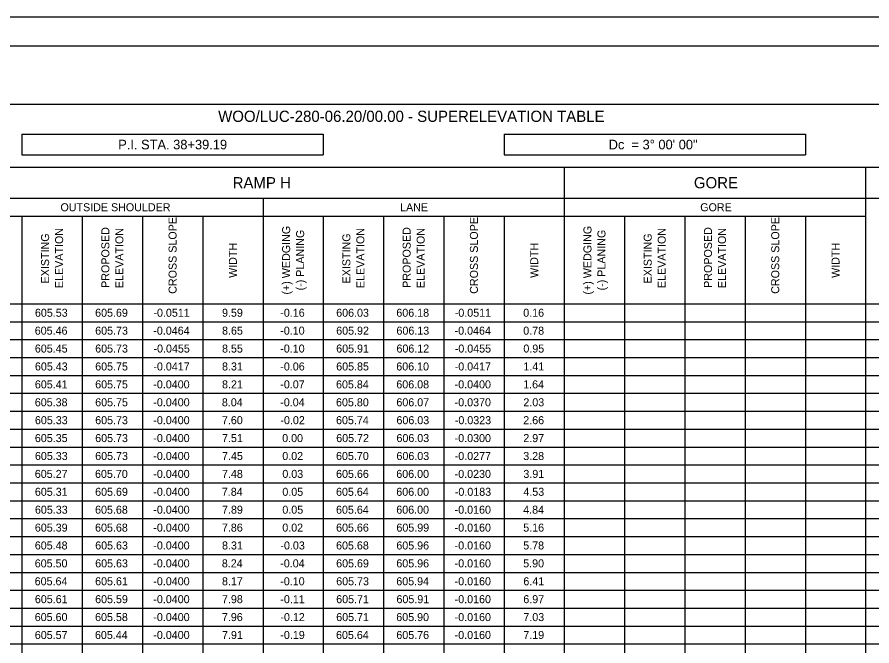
# Model space of a CAD drawing. Extents: x 0 to 34, y 0 to 22.
# Drawn here: x 7.6 to 22.56, y 11.01 to 22 of the extents above; entities that cross this region are included whole.
import ezdxf

# ---------------------------------------------------------------- set-up
doc = ezdxf.new("R2010")
doc.units = 0
for name, color, linetype in [('Default', 7, 'Continuous'), ('SH_Border', 7, 'Continuous'), ('SH_Cut_Line', 7, 'Continuous')]:
    doc.layers.add(name, color=color, linetype=linetype)

msp = doc.modelspace()

# ---------------------------------------------------------------- linework, layer by layer
at = {"layer": 'Default'}
for p, q in [((6.635, 20.48), (26.861, 20.48)), ((7.689, 19.953), (12.96, 19.953)), ((7.689, 19.953), (7.689, 19.591)), ((12.96, 19.953), (12.96, 19.591)), ((16.122, 19.953), (21.393, 19.953)), ((16.122, 19.953), (16.122, 19.591)), ((21.393, 19.953), (21.393, 19.591)), ((7.689, 19.591), (12.96, 19.591)), ((16.122, 19.591), (21.393, 19.591)), ((6.635, 19.376), (26.861, 19.376)), ((17.176, 19.376), (17.176, 1.522)), ((22.447, 19.376), (22.447, 1.522)), ((6.635, 18.833), (26.861, 18.833)), ((11.906, 18.833), (11.906, 1.522)), ((6.635, 18.52), (22.447, 18.52)), ((7.689, 18.52), (7.689, 1.522)), ((8.743, 18.52), (8.743, 1.522)), ((9.797, 18.52), (9.797, 1.522)), ((10.851, 18.52), (10.851, 1.522)), ((12.96, 18.52), (12.96, 1.522)), ((14.014, 18.52), (14.014, 1.522)), ((15.068, 18.52), (15.068, 1.522)), ((16.122, 18.52), (16.122, 1.522)), ((18.23, 18.52), (18.23, 1.522)), ((19.284, 18.52), (19.284, 1.522)), ((20.339, 18.52), (20.339, 1.522)), ((21.393, 18.52), (21.393, 1.522)), ((6.635, 16.988), (26.861, 16.988)), ((6.635, 16.675), (26.861, 16.675)), ((6.635, 16.362), (26.861, 16.362)), ((6.635, 16.049), (26.861, 16.049)), ((6.635, 15.736), (26.861, 15.736)), ((6.635, 15.424), (26.861, 15.424)), ((6.635, 15.111), (26.861, 15.111)), ((6.635, 14.798), (26.861, 14.798)), ((6.635, 14.485), (26.861, 14.485)), ((6.635, 14.172), (26.861, 14.172)), ((6.635, 13.859), (26.861, 13.859)), ((6.635, 13.546), (26.861, 13.546)), ((6.635, 13.233), (26.861, 13.233)), ((6.635, 12.92), (26.861, 12.92)), ((6.635, 12.607), (26.861, 12.607)), ((6.635, 12.294), (26.861, 12.294)), ((6.635, 11.981), (26.861, 11.981)), ((6.635, 11.668), (26.861, 11.668)), ((6.635, 11.355), (26.861, 11.355)), ((6.635, 11.042), (26.861, 11.042))]:
    msp.add_line(p, q, dxfattribs=at)
at = {"layer": 'SH_Border'}
msp.add_lwpolyline([(1.5, 21.5), (33.5, 21.5), (33.5, 0.5), (1.5, 0.5)], close=True, dxfattribs=at)
at = {"layer": 'SH_Cut_Line'}
msp.add_lwpolyline([(0, 0), (34, 0), (34, 22), (0, 22)], close=True, dxfattribs=at)

# ---------------------------------------------------------------- texts
at = {"layer": 'Default'}
for s, height, p in [('WOO/LUC-280-06.20/00.00 - SUPERELEVATION TABLE', 0.196, (11.121, 20.168)), ('P.I. STA. 38+39.19', 0.168, (9.373, 19.688)), ('Dc  = 3° 00\' 00"', 0.168, (17.952, 19.688)), ('RAMP H', 0.196, (11.374, 19.007)), ('GORE', 0.196, (19.443, 19.007)), ('OUTSIDE SHOULDER', 0.14, (8.363, 18.606)), ('LANE', 0.14, (14.304, 18.606)), ('GORE', 0.14, (19.554, 18.606)), ('605.53', 0.14, (7.916, 16.762)), ('605.69', 0.14, (8.969, 16.762)), ('-0.0511', 0.14, (9.989, 16.762)), ('9.59', 0.14, (11.189, 16.762)), ('-0.16', 0.14, (12.208, 16.762)), ('606.03', 0.14, (13.186, 16.762)), ('606.18', 0.14, (14.238, 16.762)), ('-0.0511', 0.14, (15.26, 16.762)), ('0.16', 0.14, (16.458, 16.762)), ('605.46', 0.14, (7.913, 16.449)), ('605.73', 0.14, (8.97, 16.449)), ('-0.0464', 0.14, (9.987, 16.449)), ('8.65', 0.14, (11.189, 16.449)), ('-0.10', 0.14, (12.207, 16.449)), ('605.92', 0.14, (13.186, 16.449)), ('606.13', 0.14, (14.24, 16.449)), ('-0.0464', 0.14, (15.257, 16.449)), ('0.78', 0.14, (16.458, 16.449)), ('605.45', 0.14, (7.915, 16.136)), ('605.73', 0.14, (8.97, 16.136)), ('-0.0455', 0.14, (9.99, 16.136)), ('8.55', 0.14, (11.189, 16.136)), ('-0.10', 0.14, (12.207, 16.136)), ('605.91', 0.14, (13.186, 16.136)), ('606.12', 0.14, (14.24, 16.136)), ('-0.0455', 0.14, (15.26, 16.136)), ('0.95', 0.14, (16.46, 16.136)), ('605.43', 0.14, (7.916, 15.823)), ('605.75', 0.14, (8.97, 15.823)), ('-0.0417', 0.14, (9.988, 15.823)), ('8.31', 0.14, (11.189, 15.823)), ('-0.06', 0.14, (12.208, 15.823)), ('605.85', 0.14, (13.186, 15.823)), ('606.10', 0.14, (14.237, 15.823)), ('-0.0417', 0.14, (15.259, 15.823)), ('1.41', 0.14, (16.46, 15.823)), ('605.41', 0.14, (7.915, 15.51)), ('605.75', 0.14, (8.97, 15.51)), ('-0.0400', 0.14, (9.987, 15.51)), ('8.21', 0.14, (11.189, 15.51)), ('-0.07', 0.14, (12.208, 15.51)), ('605.84', 0.14, (13.183, 15.51)), ('606.08', 0.14, (14.238, 15.51)), ('-0.0400', 0.14, (15.258, 15.51)), ('1.64', 0.14, (16.457, 15.51)), ('605.38', 0.14, (7.914, 15.197)), ('605.75', 0.14, (8.97, 15.197)), ('-0.0400', 0.14, (9.987, 15.197)), ('8.04', 0.14, (11.186, 15.197)), ('-0.04', 0.14, (12.207, 15.197)), ('605.80', 0.14, (13.183, 15.197)), ('606.07', 0.14, (14.239, 15.197)), ('-0.0370', 0.14, (15.258, 15.197)), ('2.03', 0.14, (16.46, 15.197)), ('605.33', 0.14, (7.916, 14.884)), ('605.73', 0.14, (8.97, 14.884)), ('-0.0400', 0.14, (9.987, 14.884)), ('7.60', 0.14, (11.187, 14.884)), ('-0.02', 0.14, (12.21, 14.884)), ('605.74', 0.14, (13.183, 14.884)), ('606.03', 0.14, (14.24, 14.884)), ('-0.0323', 0.14, (15.261, 14.884)), ('2.66', 0.14, (16.458, 14.884)), ('605.35', 0.14, (7.915, 14.571)), ('605.73', 0.14, (8.97, 14.571)), ('-0.0400', 0.14, (9.987, 14.571)), ('7.51', 0.14, (11.189, 14.571)), ('0.00', 0.14, (12.241, 14.571)), ('605.72', 0.14, (13.186, 14.571)), ('606.03', 0.14, (14.24, 14.571)), ('-0.0300', 0.14, (15.258, 14.571)), ('2.97', 0.14, (16.459, 14.571)), ('605.33', 0.14, (7.916, 14.258)), ('605.73', 0.14, (8.97, 14.258)), ('-0.0400', 0.14, (9.987, 14.258)), ('7.45', 0.14, (11.189, 14.258)), ('0.02', 0.14, (12.243, 14.258)), ('605.70', 0.14, (13.183, 14.258)), ('606.03', 0.14, (14.24, 14.258)), ('-0.0277', 0.14, (15.259, 14.258)), ('3.28', 0.14, (16.458, 14.258)), ('605.27', 0.14, (7.914, 13.945)), ('605.70', 0.14, (8.967, 13.945)), ('-0.0400', 0.14, (9.987, 13.945)), ('7.48', 0.14, (11.188, 13.945)), ('0.03', 0.14, (12.244, 13.945)), ('605.66', 0.14, (13.184, 13.945)), ('606.00', 0.14, (14.237, 13.945)), ('-0.0230', 0.14, (15.258, 13.945)), ('3.91', 0.14, (16.46, 13.945)), ('605.31', 0.14, (7.915, 13.632)), ('605.69', 0.14, (8.969, 13.632)), ('-0.0400', 0.14, (9.987, 13.632)), ('7.84', 0.14, (11.186, 13.632)), ('0.05', 0.14, (12.244, 13.632)), ('605.64', 0.14, (13.183, 13.632)), ('606.00', 0.14, (14.237, 13.632)), ('-0.0183', 0.14, (15.261, 13.632)), ('4.53', 0.14, (16.46, 13.632)), ('605.33', 0.14, (7.916, 13.319)), ('605.68', 0.14, (8.968, 13.319)), ('-0.0400', 0.14, (9.987, 13.319)), ('7.89', 0.14, (11.189, 13.319)), ('0.05', 0.14, (12.244, 13.319)), ('605.64', 0.14, (13.183, 13.319)), ('606.00', 0.14, (14.237, 13.319)), ('-0.0160', 0.14, (15.258, 13.319)), ('4.84', 0.14, (16.457, 13.319)), ('605.39', 0.14, (7.915, 13.006)), ('605.68', 0.14, (8.968, 13.006)), ('-0.0400', 0.14, (9.987, 13.006)), ('7.86', 0.14, (11.187, 13.006)), ('0.02', 0.14, (12.243, 13.006)), ('605.66', 0.14, (13.184, 13.006)), ('605.99', 0.14, (14.239, 13.006)), ('-0.0160', 0.14, (15.258, 13.006)), ('5.16', 0.14, (16.458, 13.006)), ('605.48', 0.14, (7.914, 12.694)), ('605.63', 0.14, (8.97, 12.694)), ('-0.0400', 0.14, (9.987, 12.694)), ('8.31', 0.14, (11.189, 12.694)), ('-0.03', 0.14, (12.21, 12.694)), ('605.68', 0.14, (13.184, 12.694)), ('605.96', 0.14, (14.238, 12.694)), ('-0.0160', 0.14, (15.258, 12.694)), ('5.78', 0.14, (16.458, 12.694)), ('605.50', 0.14, (7.913, 12.381)), ('605.63', 0.14, (8.97, 12.381)), ('-0.0400', 0.14, (9.987, 12.381)), ('8.24', 0.14, (11.186, 12.381)), ('-0.04', 0.14, (12.207, 12.381)), ('605.69', 0.14, (13.185, 12.381)), ('605.96', 0.14, (14.238, 12.381)), ('-0.0160', 0.14, (15.258, 12.381)), ('5.90', 0.14, (16.457, 12.381)), ('605.64', 0.14, (7.912, 12.068)), ('605.61', 0.14, (8.969, 12.068)), ('-0.0400', 0.14, (9.987, 12.068)), ('8.17', 0.14, (11.188, 12.068)), ('-0.10', 0.14, (12.207, 12.068)), ('605.73', 0.14, (13.186, 12.068)), ('605.94', 0.14, (14.237, 12.068)), ('-0.0160', 0.14, (15.258, 12.068)), ('6.41', 0.14, (16.46, 12.068)), ('605.61', 0.14, (7.915, 11.755)), ('605.59', 0.14, (8.969, 11.755)), ('-0.0400', 0.14, (9.987, 11.755)), ('7.98', 0.14, (11.188, 11.755)), ('-0.11', 0.14, (12.209, 11.755)), ('605.71', 0.14, (13.186, 11.755)), ('605.91', 0.14, (14.24, 11.755)), ('-0.0160', 0.14, (15.258, 11.755)), ('6.97', 0.14, (16.459, 11.755)), ('605.60', 0.14, (7.913, 11.442)), ('605.58', 0.14, (8.968, 11.442)), ('-0.0400', 0.14, (9.987, 11.442)), ('7.96', 0.14, (11.187, 11.442)), ('-0.12', 0.14, (12.21, 11.442)), ('605.71', 0.14, (13.186, 11.442)), ('605.90', 0.14, (14.237, 11.442)), ('-0.0160', 0.14, (15.258, 11.442)), ('7.03', 0.14, (16.46, 11.442)), ('605.57', 0.14, (7.914, 11.129)), ('605.44', 0.14, (8.966, 11.129)), ('-0.0400', 0.14, (9.987, 11.129)), ('7.91', 0.14, (11.189, 11.129)), ('-0.19', 0.14, (12.209, 11.129)), ('605.64', 0.14, (13.183, 11.129)), ('605.76', 0.14, (14.238, 11.129)), ('-0.0160', 0.14, (15.258, 11.129)), ('7.19', 0.14, (16.459, 11.129))]:
    msp.add_text(s, height=height, dxfattribs=at).set_placement(p)
for s, p in [('CROSS SLOPE', (10.394, 17.163)), ('CROSS SLOPE', (15.665, 17.163)), ('CROSS SLOPE', (20.936, 17.163)), ('ELEVATION', (8.409, 17.263)), ('PROPOSED ', (9.218, 17.267)), ('ELEVATION', (9.463, 17.263)), ('(+) WEDGING', (12.38, 17.15)), ('(-) PLANING', (12.625, 17.222)), ('ELEVATION', (13.679, 17.263)), ('PROPOSED ', (14.488, 17.267)), ('ELEVATION', (14.733, 17.263)), ('(+) WEDGING', (17.651, 17.15)), ('(-) PLANING', (17.896, 17.222)), ('ELEVATION', (18.95, 17.263)), ('PROPOSED ', (19.759, 17.267)), ('ELEVATION', (20.004, 17.263)), ('EXISTING ', (8.164, 17.345)), ('EXISTING ', (13.434, 17.345)), ('EXISTING ', (18.705, 17.345)), ('WIDTH', (11.449, 17.441)), ('WIDTH', (16.719, 17.441)), ('WIDTH', (21.99, 17.441))]:
    msp.add_text(s, height=0.14, rotation=90, dxfattribs=at).set_placement(p)

doc.saveas('drawing.dxf')
